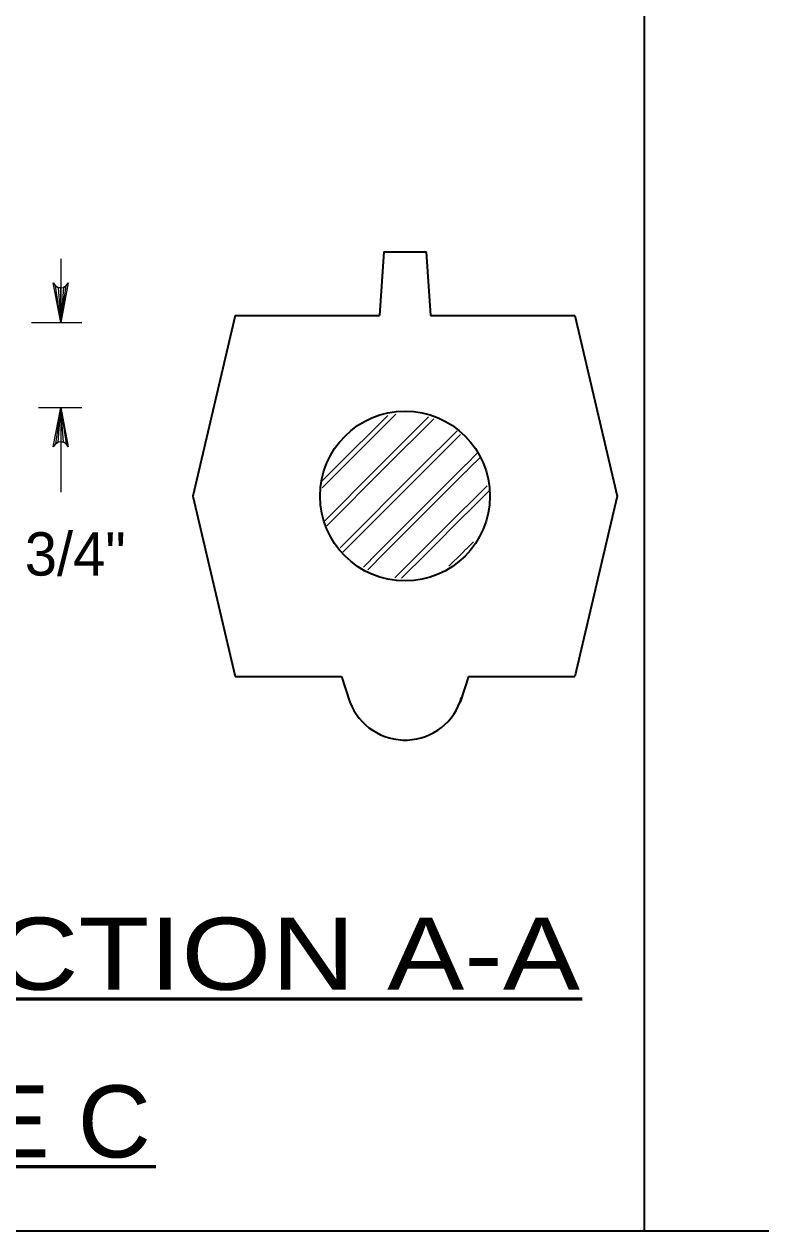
# Model space of a CAD drawing. Extents: x 15 to 140, y -57 to 117.
# Drawn here: x 45.63 to 63, y -2.09 to 26.34 of the extents above; entities that cross this region are included whole.
import ezdxf
from ezdxf.enums import TextEntityAlignment as Align

# ---------------------------------------------------------------- set-up
doc = ezdxf.new("R2010")
doc.units = 0
doc.header["$LTSCALE"] = 0.41
for name, color, linetype, lineweight in [('1', 7, 'Continuous', 35), ('10', 7, 'Continuous', 13), ('12', 7, 'Continuous', 53), ('13', 7, 'Continuous', 53), ('6', 7, 'Continuous', 13)]:
    doc.layers.add(name, color=color, linetype=linetype, lineweight=lineweight)

msp = doc.modelspace()

# ---------------------------------------------------------------- linework, layer by layer
at = {"layer": '1'}
for p, q in [((60.2522, -2.0932), (60.2522, 32.9068)), ((54.1108, 20.9705), (54.0108, 19.4705)), ((54.1108, 20.9705), (55.1108, 20.9705)), ((55.1108, 20.9705), (55.2108, 19.4705)), ((50.6108, 19.4705), (54.0108, 19.4705)), ((55.2108, 19.4705), (58.6108, 19.4705)), ((50.6108, 10.9705), (53.1108, 10.9705)), ((53.1108, 10.9705), (53.3121, 10.3666)), ((56.1108, 10.9705), (55.9097, 10.3675)), ((56.1108, 10.9705), (58.6108, 10.9705)), ((15.0728, -2.0932), (140.4342, -2.0932))]:
    msp.add_line(p, q, dxfattribs=at)
for points in [[(50.6108, 19.4705), (49.6108, 15.2205), (50.6108, 10.9705)], [(58.6108, 19.4705), (59.6108, 15.2205), (58.6108, 10.9705)]]:
    msp.add_lwpolyline(points, dxfattribs=at)
msp.add_circle((54.6108, 15.2205), 2, dxfattribs=at)
msp.add_arc((54.6108, 10.8597), 1.3891, 200.79114, 343.88139, dxfattribs=at)
at = {"layer": '10'}
for p, q in [((46.496, 20.8097), (46.496, 19.3097)), ((45.808, 19.3097), (46.996, 19.3097)), ((45.9746, 17.3097), (46.996, 17.3097)), ((46.496, 17.3097), (46.496, 15.3097))]:
    msp.add_line(p, q, dxfattribs=at)
for points in [[(46.496, 19.3097), (46.3212, 20.2418), (46.371, 20.17), (46.4335, 20.133), (46.496, 20.1222), (46.5585, 20.133), (46.621, 20.17), (46.6707, 20.2418), (46.496, 19.3097), (46.621, 20.17), (46.5585, 20.133), (46.496, 19.3097), (46.496, 20.1222), (46.4335, 20.133), (46.496, 19.3097), (46.371, 20.17)], [(46.496, 17.3097), (46.6707, 16.3777), (46.621, 16.4495), (46.5585, 16.4865), (46.496, 16.4972), (46.4335, 16.4865), (46.371, 16.4495), (46.3212, 16.3777), (46.496, 17.3097), (46.371, 16.4495), (46.4335, 16.4865), (46.496, 17.3097), (46.496, 16.4972), (46.5585, 16.4865), (46.496, 17.3097), (46.621, 16.4495)]]:
    msp.add_lwpolyline(points, dxfattribs=at)
at = {"layer": '12'}
for p, q in [((41.2528, 3.3742), (58.7891, 3.3742)), ((39.8852, -0.5764), (48.7353, -0.5764))]:
    msp.add_line(p, q, dxfattribs=at)
at = {"layer": '6'}
for p, q in [((52.9627, 15.8816), (54.202, 17.1209)), ((53.1294, 15.8816), (54.3981, 17.1503)), ((53.9627, 15.8816), (55.164, 17.0829)), ((54.1294, 15.8816), (55.2869, 17.0391)), ((54.9627, 15.8816), (55.8371, 16.756)), ((55.1294, 15.8816), (55.9164, 16.6686)), ((56.0497, 15.9649), (56.3146, 16.2298)), ((55.9627, 15.8816), (56.046, 15.9649)), ((56.133, 15.8816), (56.3825, 16.131)), ((52.6502, 15.569), (52.9627, 15.8816)), ((52.6584, 15.4106), (53.1294, 15.8816)), ((52.705, 14.6239), (53.9627, 15.8816)), ((52.7677, 14.5199), (54.1294, 15.8816)), ((53.0814, 14.0002), (54.9627, 15.8816)), ((53.1441, 13.8963), (55.1294, 15.8816)), ((53.9627, 13.8816), (55.9627, 15.8816)), ((54.1294, 13.8816), (56.046, 15.7982)), ((56.133, 15.8816), (56.046, 15.7946)), ((56.0497, 14.9649), (56.5496, 15.4647)), ((56.583, 15.3315), (56.0497, 14.7982)), ((54.9627, 13.8816), (56.046, 14.9649)), ((55.1294, 13.8816), (56.046, 14.7982)), ((55.9627, 13.8816), (56.046, 13.9649)), ((56.0497, 13.9649), (56.2223, 14.1375)), ((53.6286, 13.5475), (53.9627, 13.8816)), ((53.7332, 13.4854), (54.1294, 13.8816)), ((54.3706, 13.2895), (54.9627, 13.8816)), ((54.53, 13.2822), (55.1294, 13.8816)), ((55.6467, 13.5655), (55.9627, 13.8816))]:
    msp.add_line(p, q, dxfattribs=at)

# ---------------------------------------------------------------- texts
at = {"layer": '12'}
for s, width, p in [('SECTION A-A', 1.2, (50.021, 3.5867)), ('TYPE C', 1.05, (44.3102, -0.3639))]:
    msp.add_text(s, height=1.7, dxfattribs=dict(at, width=width)).set_placement(p, align=Align.CENTER)
at = {"layer": '13'}
msp.add_text('3/4"', height=1.02, dxfattribs=at).set_placement((46.8401, 13.3465), align=Align.CENTER)

doc.saveas('drawing.dxf')
